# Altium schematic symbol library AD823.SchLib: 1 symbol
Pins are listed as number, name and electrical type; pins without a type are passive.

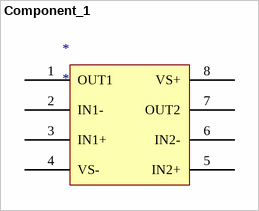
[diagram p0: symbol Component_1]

## Component_1
designator *
pins: 1 OUT1, 2 IN1-, 3 IN1+, 4 VS-, 5 IN2+, 6 IN2-, 7 OUT2, 8 VS+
